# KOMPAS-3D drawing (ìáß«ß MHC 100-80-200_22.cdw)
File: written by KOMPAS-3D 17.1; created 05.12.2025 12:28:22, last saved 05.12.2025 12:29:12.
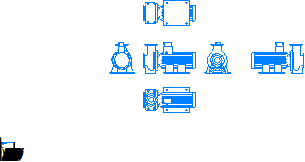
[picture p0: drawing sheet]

Sheet 1: A4, portrait

Title block, sheet 1: name: Насос MHC / 100-80-200_22; material: Сталь 10  ГОСТ 1050-88; mass: 310,89; sheets: 1; sheet format: A4

Views: Проекционный вид 2, Проекционный вид 3, Проекционный вид 4, Проекционный вид 5, Проекционный вид 6
Referenced files in \\adlc.lan\data\АДЛ_ПКД\3D-модели\ADL production\Насосы ГРАНПАМП\Насосы ГРАНПАМП серии МНС\KOMPAS 3D\: Насос MHC 100-80-200_22.m3d
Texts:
  Andrey
  АДЛ
Dimensions and other numbers on the sheet: 1:1; 1; 100-80-200_22; 310,89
